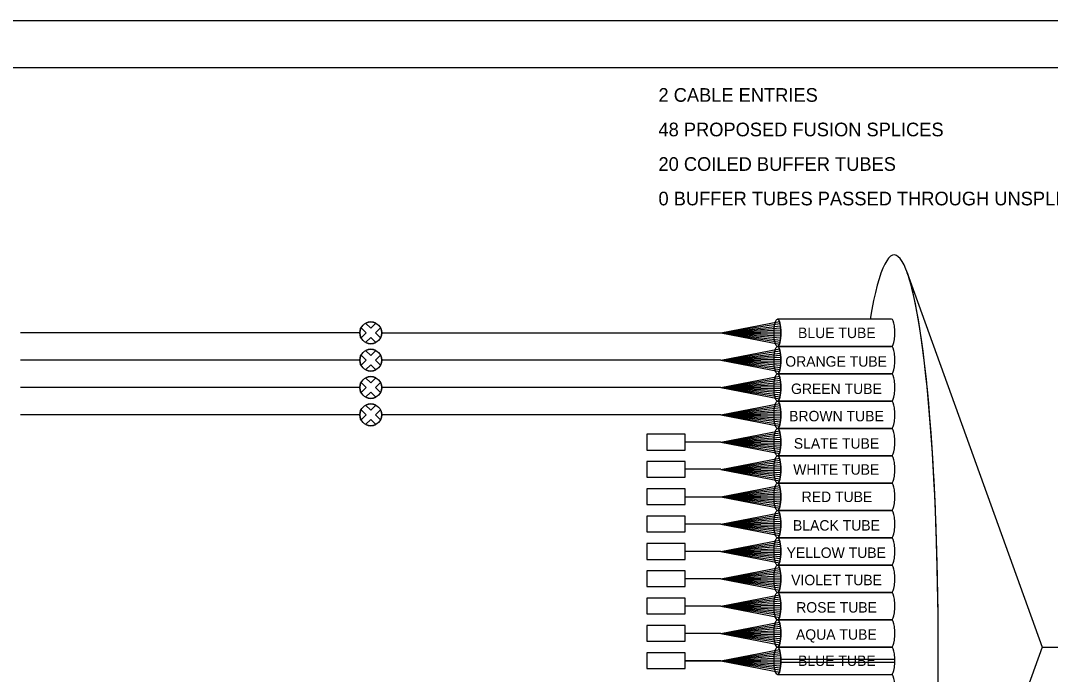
# Model space of a CAD drawing. Extents: x 1805893 to 1833564, y 708898 to 716199.
# Drawn here: x 1833208.6 to 1833434.8, y 714395 to 714538.6 of the extents above; entities that cross this region are included whole.
import ezdxf

# ---------------------------------------------------------------- set-up
doc = ezdxf.new("R2010")
doc.units = 0
doc.layers.add('BR_P_Sub_Hidden', color=7, linetype='Continuous')
doc.layers.add('SH_Data', color=7, linetype='Continuous')

msp = doc.modelspace()

# ---------------------------------------------------------------- linework, layer by layer
at = {"layer": 'BR_P_Sub_Hidden'}
for points in [[(1833067.2, 714538.6), (1833508.62, 714538.6), (1833508.62, 714273.91), (1833067.2, 714273.91)], [(1833135.95, 714528.32), (1833459.05, 714528.32), (1833459.05, 714279.3), (1833135.95, 714279.3)]]:
    msp.add_lwpolyline(points, close=True, dxfattribs=at)
at = {"layer": 'SH_Data'}
for p, q in [((1833362.41, 714470.04), (1833375.25, 714472.51)), ((1833399.88, 714473.04), (1833374.83, 714473.04)), ((1833399.88, 714473.04), (1833374.83, 714473.04)), ((1833284.46, 714470.04), (1833283.34, 714471.16)), ((1833284.46, 714470.04), (1833283.34, 714471.16)), ((1833285.48, 714471.05), (1833284.36, 714472.17)), ((1833284.36, 714472.17), (1833285.48, 714471.05)), ((1833286.6, 714472.17), (1833285.48, 714471.05)), ((1833285.48, 714471.05), (1833286.6, 714472.17)), ((1833287.61, 714471.16), (1833286.5, 714470.04)), ((1833287.61, 714471.16), (1833286.5, 714470.04)), ((1833362.41, 714470.04), (1833375.38, 714472.06)), ((1833362.41, 714470.04), (1833375.46, 714471.61)), ((1833362.41, 714470.04), (1833375.52, 714471.16)), ((1833362.41, 714470.04), (1833375.56, 714470.71)), ((1833362.41, 714470.04), (1833375.57, 714470.26)), ((1833283.07, 714470.04), (1833208.55, 714470.04)), ((1833284.46, 714470.04), (1833283.34, 714468.92)), ((1833283.34, 714468.92), (1833284.46, 714470.04)), ((1833285.48, 714469.02), (1833284.36, 714467.9)), ((1833285.48, 714469.02), (1833284.36, 714467.9)), ((1833286.6, 714467.9), (1833285.48, 714469.02)), ((1833286.6, 714467.9), (1833285.48, 714469.02)), ((1833287.61, 714468.92), (1833286.5, 714470.04)), ((1833286.5, 714470.04), (1833287.61, 714468.92)), ((1833287.89, 714470.04), (1833362.41, 714470.04)), ((1833362.41, 714470.04), (1833375.52, 714468.91)), ((1833362.41, 714470.04), (1833375.46, 714468.46)), ((1833362.41, 714470.04), (1833375.38, 714468.01)), ((1833362.41, 714470.04), (1833375.25, 714467.56)), ((1833362.41, 714470.04), (1833375.56, 714469.36)), ((1833362.41, 714470.04), (1833375.57, 714469.81)), ((1833285.48, 714465.05), (1833284.36, 714466.17)), ((1833284.36, 714466.17), (1833285.48, 714465.05)), ((1833286.6, 714466.17), (1833285.48, 714465.05)), ((1833285.48, 714465.05), (1833286.6, 714466.17)), ((1833362.41, 714464.04), (1833375.25, 714466.51)), ((1833362.41, 714464.04), (1833375.38, 714466.06)), ((1833362.41, 714464.04), (1833375.46, 714465.61)), ((1833374.83, 714467.04), (1833399.88, 714467.04)), ((1833399.88, 714467.04), (1833374.83, 714467.04)), ((1833283.07, 714464.04), (1833208.55, 714464.04)), ((1833284.46, 714464.04), (1833283.34, 714465.16)), ((1833284.46, 714464.04), (1833283.34, 714465.16)), ((1833284.46, 714464.04), (1833283.34, 714462.92)), ((1833283.34, 714462.92), (1833284.46, 714464.04)), ((1833287.61, 714465.16), (1833286.5, 714464.04)), ((1833287.61, 714465.16), (1833286.5, 714464.04)), ((1833287.61, 714462.92), (1833286.5, 714464.04)), ((1833286.5, 714464.04), (1833287.61, 714462.92)), ((1833362.41, 714464.04), (1833287.89, 714464.04)), ((1833362.41, 714464.04), (1833375.52, 714465.16)), ((1833362.41, 714464.04), (1833375.56, 714464.71)), ((1833362.41, 714464.04), (1833375.57, 714464.26)), ((1833362.41, 714464.04), (1833375.52, 714462.91)), ((1833362.41, 714464.04), (1833375.46, 714462.46)), ((1833362.41, 714464.04), (1833375.38, 714462.01)), ((1833362.41, 714464.04), (1833375.25, 714461.56)), ((1833362.41, 714464.04), (1833375.56, 714463.36)), ((1833362.41, 714464.04), (1833375.57, 714463.81)), ((1833285.48, 714463.02), (1833284.36, 714461.9)), ((1833285.48, 714463.02), (1833284.36, 714461.9)), ((1833286.6, 714461.9), (1833285.48, 714463.02)), ((1833286.6, 714461.9), (1833285.48, 714463.02)), ((1833399.88, 714461.04), (1833374.83, 714461.04)), ((1833374.83, 714461.04), (1833399.88, 714461.04)), ((1833284.46, 714458.04), (1833283.34, 714459.16)), ((1833284.46, 714458.04), (1833283.34, 714459.16)), ((1833285.48, 714459.05), (1833284.36, 714460.17)), ((1833284.36, 714460.17), (1833285.48, 714459.05)), ((1833286.6, 714460.17), (1833285.48, 714459.05)), ((1833285.48, 714459.05), (1833286.6, 714460.17)), ((1833287.61, 714459.16), (1833286.5, 714458.04)), ((1833287.61, 714459.16), (1833286.5, 714458.04)), ((1833362.41, 714458.04), (1833375.25, 714460.51)), ((1833362.41, 714458.04), (1833375.38, 714460.06)), ((1833362.41, 714458.04), (1833375.46, 714459.61)), ((1833362.41, 714458.04), (1833375.52, 714459.16)), ((1833283.07, 714458.04), (1833208.55, 714458.04)), ((1833284.46, 714458.04), (1833283.34, 714456.92)), ((1833283.34, 714456.92), (1833284.46, 714458.04)), ((1833285.48, 714457.02), (1833284.36, 714455.9)), ((1833285.48, 714457.02), (1833284.36, 714455.9)), ((1833286.6, 714455.9), (1833285.48, 714457.02)), ((1833286.6, 714455.9), (1833285.48, 714457.02)), ((1833287.61, 714456.92), (1833286.5, 714458.04)), ((1833286.5, 714458.04), (1833287.61, 714456.92)), ((1833362.41, 714458.04), (1833287.89, 714458.04)), ((1833362.41, 714458.04), (1833375.56, 714458.71)), ((1833362.41, 714458.04), (1833375.57, 714458.26)), ((1833362.41, 714458.04), (1833375.52, 714456.91)), ((1833362.41, 714458.04), (1833375.46, 714456.46)), ((1833362.41, 714458.04), (1833375.38, 714456.01)), ((1833362.41, 714458.04), (1833375.25, 714455.56)), ((1833362.41, 714458.04), (1833375.56, 714457.36)), ((1833362.41, 714458.04), (1833375.57, 714457.81)), ((1833362.41, 714452.04), (1833375.25, 714454.51)), ((1833374.83, 714455.04), (1833399.88, 714455.04)), ((1833399.88, 714455.04), (1833374.83, 714455.04)), ((1833283.07, 714452.04), (1833208.55, 714452.04)), ((1833284.46, 714452.04), (1833283.34, 714453.16)), ((1833284.46, 714452.04), (1833283.34, 714453.16)), ((1833284.46, 714452.04), (1833283.34, 714450.92)), ((1833283.34, 714450.92), (1833284.46, 714452.04)), ((1833285.48, 714453.05), (1833284.36, 714454.17)), ((1833284.36, 714454.17), (1833285.48, 714453.05)), ((1833286.6, 714454.17), (1833285.48, 714453.05)), ((1833285.48, 714453.05), (1833286.6, 714454.17)), ((1833287.61, 714453.16), (1833286.5, 714452.04)), ((1833287.61, 714453.16), (1833286.5, 714452.04)), ((1833287.61, 714450.92), (1833286.5, 714452.04)), ((1833286.5, 714452.04), (1833287.61, 714450.92)), ((1833362.41, 714452.04), (1833287.89, 714452.04)), ((1833362.41, 714452.04), (1833375.38, 714454.06)), ((1833362.41, 714452.04), (1833375.46, 714453.61)), ((1833362.41, 714452.04), (1833375.52, 714453.16)), ((1833362.41, 714452.04), (1833375.56, 714452.71)), ((1833362.41, 714452.04), (1833375.57, 714452.26)), ((1833362.41, 714452.04), (1833375.52, 714450.91)), ((1833362.41, 714452.04), (1833375.46, 714450.46)), ((1833362.41, 714452.04), (1833375.38, 714450.01)), ((1833362.41, 714452.04), (1833375.25, 714449.56)), ((1833362.41, 714452.04), (1833375.56, 714451.36)), ((1833362.41, 714452.04), (1833375.57, 714451.81)), ((1833285.48, 714451.02), (1833284.36, 714449.9)), ((1833285.48, 714451.02), (1833284.36, 714449.9)), ((1833286.6, 714449.9), (1833285.48, 714451.02)), ((1833286.6, 714449.9), (1833285.48, 714451.02)), ((1833362.41, 714446.04), (1833375.25, 714448.51)), ((1833362.41, 714446.04), (1833375.38, 714448.06)), ((1833362.41, 714446.04), (1833375.46, 714447.61)), ((1833374.83, 714449.04), (1833399.88, 714449.04)), ((1833399.88, 714449.04), (1833374.83, 714449.04)), ((1833362.41, 714446.04), (1833354.58, 714446.04)), ((1833362.41, 714446.04), (1833375.52, 714447.16)), ((1833362.41, 714446.04), (1833375.56, 714446.71)), ((1833362.41, 714446.04), (1833375.57, 714446.26)), ((1833362.41, 714446.04), (1833375.52, 714444.91)), ((1833362.41, 714446.04), (1833375.46, 714444.46)), ((1833362.41, 714446.04), (1833375.38, 714444.01)), ((1833362.41, 714446.04), (1833375.25, 714443.56)), ((1833362.41, 714446.04), (1833375.56, 714445.36)), ((1833362.41, 714446.04), (1833375.57, 714445.81)), ((1833374.83, 714443.04), (1833399.88, 714443.04)), ((1833399.88, 714443.04), (1833374.83, 714443.04)), ((1833362.41, 714440.04), (1833375.25, 714442.51)), ((1833362.41, 714440.04), (1833375.38, 714442.06)), ((1833362.41, 714440.04), (1833375.46, 714441.61)), ((1833362.41, 714440.04), (1833375.52, 714441.16)), ((1833362.41, 714440.04), (1833375.56, 714440.71)), ((1833362.41, 714440.07), (1833354.58, 714440.07)), ((1833362.41, 714440.04), (1833375.57, 714440.26)), ((1833362.41, 714440.04), (1833375.52, 714438.91)), ((1833362.41, 714440.04), (1833375.46, 714438.46)), ((1833362.41, 714440.04), (1833375.38, 714438.01)), ((1833362.41, 714440.04), (1833375.25, 714437.56)), ((1833362.41, 714440.04), (1833375.56, 714439.36)), ((1833362.41, 714440.04), (1833375.57, 714439.81)), ((1833362.41, 714434.04), (1833375.25, 714436.51)), ((1833374.83, 714437.04), (1833399.88, 714437.04)), ((1833399.88, 714437.04), (1833374.83, 714437.04)), ((1833354.58, 714434.04), (1833362.41, 714434.04)), ((1833362.41, 714434.04), (1833375.38, 714436.06)), ((1833362.41, 714434.04), (1833375.46, 714435.61)), ((1833362.41, 714434.04), (1833375.52, 714435.16)), ((1833362.41, 714434.04), (1833375.56, 714434.71)), ((1833362.41, 714434.04), (1833375.57, 714434.26)), ((1833362.41, 714434.04), (1833375.52, 714432.91)), ((1833362.41, 714434.04), (1833375.46, 714432.46)), ((1833362.41, 714434.04), (1833375.38, 714432.01)), ((1833362.41, 714434.04), (1833375.25, 714431.56)), ((1833362.41, 714434.04), (1833375.56, 714433.36)), ((1833362.41, 714434.04), (1833375.57, 714433.81)), ((1833362.41, 714428.04), (1833375.25, 714430.51)), ((1833362.41, 714428.04), (1833375.38, 714430.06)), ((1833362.41, 714428.04), (1833375.46, 714429.61)), ((1833374.83, 714431.04), (1833399.88, 714431.04)), ((1833399.88, 714431.04), (1833374.83, 714431.04)), ((1833362.41, 714428.04), (1833354.58, 714428.04)), ((1833362.41, 714428.04), (1833375.52, 714429.16)), ((1833362.41, 714428.04), (1833375.56, 714428.71)), ((1833362.41, 714428.04), (1833375.57, 714428.26)), ((1833362.41, 714428.04), (1833375.52, 714426.91)), ((1833362.41, 714428.04), (1833375.46, 714426.46)), ((1833362.41, 714428.04), (1833375.38, 714426.01)), ((1833362.41, 714428.04), (1833375.25, 714425.56)), ((1833362.41, 714428.04), (1833375.56, 714427.36)), ((1833362.41, 714428.04), (1833375.57, 714427.81)), ((1833399.88, 714425.04), (1833374.83, 714425.04)), ((1833374.83, 714425.04), (1833399.88, 714425.04)), ((1833362.41, 714422.04), (1833375.25, 714424.51)), ((1833362.41, 714422.04), (1833375.38, 714424.06)), ((1833362.41, 714422.04), (1833375.46, 714423.61)), ((1833362.41, 714422.04), (1833375.52, 714423.16)), ((1833362.41, 714422.04), (1833375.56, 714422.71)), ((1833362.41, 714422.04), (1833354.58, 714422.04)), ((1833362.41, 714422.04), (1833375.57, 714422.26)), ((1833362.41, 714422.04), (1833375.52, 714420.91)), ((1833362.41, 714422.04), (1833375.46, 714420.46)), ((1833362.41, 714422.04), (1833375.38, 714420.01)), ((1833362.41, 714422.04), (1833375.25, 714419.56)), ((1833362.41, 714422.04), (1833375.56, 714421.36)), ((1833362.41, 714422.04), (1833375.57, 714421.81)), ((1833362.41, 714416.04), (1833375.25, 714418.51)), ((1833362.41, 714416.04), (1833375.38, 714418.06)), ((1833374.83, 714419.04), (1833399.88, 714419.04)), ((1833399.88, 714419.04), (1833374.83, 714419.04)), ((1833399.88, 714419.04), (1833374.83, 714419.04)), ((1833362.41, 714416.04), (1833354.58, 714416.04)), ((1833362.41, 714416.04), (1833375.46, 714417.61)), ((1833362.41, 714416.04), (1833375.52, 714417.16)), ((1833362.41, 714416.04), (1833375.56, 714416.71)), ((1833362.41, 714416.04), (1833375.57, 714416.26)), ((1833362.41, 714416.04), (1833375.52, 714414.91)), ((1833362.41, 714416.04), (1833375.46, 714414.46)), ((1833362.41, 714416.04), (1833375.38, 714414.01)), ((1833362.41, 714416.04), (1833375.25, 714413.56)), ((1833362.41, 714416.04), (1833375.56, 714415.36)), ((1833362.41, 714416.04), (1833375.57, 714415.81)), ((1833362.41, 714410.04), (1833375.25, 714412.51)), ((1833362.41, 714410.04), (1833375.38, 714412.06)), ((1833362.41, 714410.04), (1833375.46, 714411.61)), ((1833374.83, 714413.04), (1833399.88, 714413.04)), ((1833399.88, 714413.04), (1833374.83, 714413.04)), ((1833362.41, 714410.04), (1833354.58, 714410.04)), ((1833362.41, 714410.04), (1833375.52, 714411.16)), ((1833362.41, 714410.04), (1833375.56, 714410.71)), ((1833362.41, 714410.04), (1833375.57, 714410.26)), ((1833362.41, 714410.04), (1833375.52, 714408.91)), ((1833362.41, 714410.04), (1833375.46, 714408.46)), ((1833362.41, 714410.04), (1833375.38, 714408.01)), ((1833362.41, 714410.04), (1833375.25, 714407.56)), ((1833362.41, 714410.04), (1833375.56, 714409.36)), ((1833362.41, 714410.04), (1833375.57, 714409.81)), ((1833374.83, 714407.04), (1833399.88, 714407.04)), ((1833399.88, 714407.04), (1833374.83, 714407.04)), ((1833362.41, 714404.04), (1833375.25, 714406.51)), ((1833362.41, 714404.04), (1833375.38, 714406.06)), ((1833362.41, 714404.04), (1833375.46, 714405.61)), ((1833362.41, 714404.04), (1833375.52, 714405.16)), ((1833362.41, 714404.04), (1833375.56, 714404.71)), ((1833362.41, 714404.04), (1833354.58, 714404.03)), ((1833362.41, 714404.04), (1833375.57, 714404.26)), ((1833362.41, 714404.04), (1833375.52, 714402.91)), ((1833362.41, 714404.04), (1833375.46, 714402.46)), ((1833362.41, 714404.04), (1833375.38, 714402.01)), ((1833362.41, 714404.04), (1833375.25, 714401.56)), ((1833362.41, 714404.04), (1833375.56, 714403.36)), ((1833362.41, 714404.04), (1833375.57, 714403.81)), ((1833362.41, 714398.04), (1833375.25, 714400.51)), ((1833362.41, 714398.04), (1833375.38, 714400.06)), ((1833374.83, 714401.04), (1833399.88, 714401.04)), ((1833399.88, 714401.04), (1833374.83, 714401.04)), ((1833432.95, 714401.04), (1833476.52, 714401.04)), ((1833362.41, 714398.04), (1833354.58, 714398.04)), ((1833354.58, 714398.04), (1833362.41, 714398.04)), ((1833362.41, 714398.04), (1833375.46, 714399.61)), ((1833362.41, 714398.04), (1833375.52, 714399.16)), ((1833362.41, 714398.04), (1833375.56, 714398.71)), ((1833362.41, 714398.04), (1833375.57, 714398.26)), ((1833362.41, 714398.04), (1833375.52, 714396.91)), ((1833362.41, 714398.04), (1833375.46, 714396.46)), ((1833362.41, 714398.04), (1833375.38, 714396.01)), ((1833362.41, 714398.04), (1833375.25, 714395.56)), ((1833362.41, 714398.04), (1833375.56, 714397.36)), ((1833362.41, 714398.04), (1833375.57, 714397.81)), ((1833374.83, 714395.04), (1833399.88, 714395.04))]:
    msp.add_line(p, q, dxfattribs=at)
msp.add_lwpolyline([(1833403.35, 714483.23), (1833432.95, 714401.04), (1833403.35, 714318.84)], dxfattribs=at)
msp.add_lwpolyline([(1833403.35, 714483.23), (1833432.95, 714401.04), (1833403.35, 714318.84)], dxfattribs=at)
for points in [[(1833354.58, 714444.31), (1833354.58, 714447.77), (1833346.13, 714447.77), (1833346.13, 714444.31)], [(1833354.58, 714438.31), (1833354.58, 714441.77), (1833346.13, 714441.77), (1833346.13, 714438.31)], [(1833354.58, 714432.34), (1833354.58, 714435.8), (1833346.13, 714435.8), (1833346.13, 714432.34)], [(1833354.58, 714426.35), (1833354.58, 714429.81), (1833346.13, 714429.81), (1833346.13, 714426.35)], [(1833354.58, 714420.3), (1833354.58, 714423.76), (1833346.13, 714423.76), (1833346.13, 714420.3)], [(1833354.58, 714414.31), (1833354.58, 714417.77), (1833346.13, 714417.77), (1833346.13, 714414.31)], [(1833354.58, 714408.34), (1833354.58, 714411.8), (1833346.13, 714411.8), (1833346.13, 714408.34)], [(1833354.58, 714402.34), (1833354.58, 714405.8), (1833346.13, 714405.8), (1833346.13, 714402.34)], [(1833354.58, 714396.31), (1833354.58, 714399.77), (1833346.13, 714399.77), (1833346.13, 714396.31)], [(1833400.62, 714398.34), (1833375.57, 714398.34), (1833375.57, 714397.74), (1833400.62, 714397.74)]]:
    msp.add_lwpolyline(points, close=True, dxfattribs=at)
for centre in [(1833285.48, 714470.04), (1833285.48, 714464.04), (1833285.48, 714458.04), (1833285.48, 714452.04)]:
    msp.add_circle(centre, 2.41, dxfattribs=at)
for centre, start, end in [((1833285.48, 714470.04), 62.353, 117.647), ((1833285.48, 714470.04), 152.353, 207.647), ((1833285.48, 714470.04), 332.353, 27.647), ((1833285.48, 714470.04), 242.353, 297.647), ((1833285.48, 714464.04), 62.353, 117.647), ((1833285.48, 714464.04), 152.353, 207.647), ((1833285.48, 714464.04), 332.353, 27.647), ((1833285.48, 714464.04), 242.353, 297.647), ((1833285.48, 714458.04), 152.353, 207.647), ((1833285.48, 714458.04), 62.353, 117.647), ((1833285.48, 714458.04), 332.353, 27.647), ((1833285.48, 714458.04), 242.353, 297.647), ((1833285.48, 714452.04), 62.353, 117.647), ((1833285.48, 714452.04), 152.353, 207.647), ((1833285.48, 714452.04), 332.353, 27.647), ((1833285.48, 714452.04), 242.353, 297.647)]:
    msp.add_arc(centre, 2.41, start, end, dxfattribs=at)
for centre, major_axis, ratio, start_param, end_param in [((1833400.48, 714401.04), (0, -86.09), 0.112175, 5.702888, 10.005075), ((1833400.48, 714401.04), (0, -86.09), 0.112175, 5.702888, 10.005075), ((1833400.48, 714401.04), (0, -86.09), 0.112175, 0.302036, 2.839557), ((1833374.83, 714470.04), (0, -3), 0.25, 0, 3.141593), ((1833399.88, 714470.04), (0, -3), 0.25, 0, 3.141593), ((1833399.88, 714470.04), (0, -3), 0.25, 0, 3.141593), ((1833374.83, 714464.04), (0, -3), 0.25, 0, 3.141593), ((1833399.88, 714464.04), (0, -3), 0.25, 0, 3.141593), ((1833399.88, 714464.04), (0, -3), 0.25, 0, 3.141593), ((1833374.83, 714458.04), (0, -3), 0.25, 0, 3.141593), ((1833399.88, 714458.04), (0, -3), 0.25, 0, 3.141593), ((1833399.88, 714458.04), (0, -3), 0.25, 0, 3.141593), ((1833374.83, 714452.04), (0, -3), 0.25, 0, 3.141593), ((1833399.88, 714452.04), (0, -3), 0.25, 0, 3.141593), ((1833399.88, 714452.04), (0, -3), 0.25, 0, 3.141593), ((1833374.83, 714446.04), (0, -3), 0.25, 0, 3.141593), ((1833399.88, 714446.04), (0, -3), 0.25, 0, 3.141593), ((1833399.88, 714446.04), (0, -3), 0.25, 0, 3.141593), ((1833374.83, 714440.04), (0, -3), 0.25, 0, 3.141593), ((1833399.88, 714440.04), (0, -3), 0.25, 0, 3.141593), ((1833399.88, 714440.04), (0, -3), 0.25, 0, 3.141593), ((1833374.83, 714434.04), (0, -3), 0.25, 0, 3.141593), ((1833399.88, 714434.04), (0, -3), 0.25, 0, 3.141593), ((1833399.88, 714434.04), (0, -3), 0.25, 0, 3.141593), ((1833374.83, 714428.04), (0, -3), 0.25, 0, 3.141593), ((1833399.88, 714428.04), (0, -3), 0.25, 0, 3.141593), ((1833399.88, 714428.04), (0, -3), 0.25, 0, 3.141593), ((1833374.83, 714422.04), (0, -3), 0.25, 0, 3.141593), ((1833399.88, 714422.04), (0, -3), 0.25, 0, 3.141593), ((1833399.88, 714422.04), (0, -3), 0.25, 0, 3.141593), ((1833374.83, 714416.04), (0, -3), 0.25, 0, 3.141593), ((1833399.88, 714416.04), (0, -3), 0.25, 0, 3.141593), ((1833399.88, 714416.04), (0, -3), 0.25, 0, 3.141593), ((1833374.83, 714410.04), (0, -3), 0.25, 0, 3.141593), ((1833399.88, 714410.04), (0, -3), 0.25, 0, 3.141593), ((1833399.88, 714410.04), (0, -3), 0.25, 0, 3.141593), ((1833374.83, 714404.04), (0, -3), 0.25, 0, 3.141593), ((1833399.88, 714404.04), (0, -3), 0.25, 0, 3.141593), ((1833399.88, 714404.04), (0, -3), 0.25, 0, 3.141593), ((1833374.83, 714398.04), (0, -3), 0.25, 0, 3.141593), ((1833399.88, 714398.04), (0, -3), 0.25, 0, 3.141593), ((1833399.88, 714398.04), (0, -3), 0.25, 0, 3.141593), ((1833399.88, 714392.04), (0, -3), 0.25, 0, 3.141593)]:
    msp.add_ellipse(centre, major_axis=major_axis, ratio=ratio, start_param=start_param, end_param=end_param, dxfattribs=at)
for centre in [(1833374.83, 714470.04), (1833374.83, 714464.04), (1833374.83, 714458.04), (1833374.83, 714452.04), (1833374.83, 714446.04), (1833374.83, 714440.04), (1833374.83, 714434.04), (1833374.83, 714428.04), (1833374.83, 714422.04), (1833374.83, 714416.04), (1833374.83, 714410.04), (1833374.83, 714404.04), (1833374.83, 714398.04)]:
    msp.add_ellipse(centre, major_axis=(0, -3), ratio=0.25, dxfattribs=at)

# ---------------------------------------------------------------- texts
for s, p in [('2 CABLE ENTRIES', (1833348.69, 714520.77)), ('48 PROPOSED FUSION SPLICES', (1833348.69, 714513.19)), ('20 COILED BUFFER TUBES', (1833348.69, 714505.61)), ('0 BUFFER TUBES PASSED THROUGH UNSPLICED', (1833348.69, 714498.03))]:
    msp.add_text(s, height=3, dxfattribs=at).set_placement(p)
for s, height, p in [('BLUE TUBE', 2.295, (1833379.35, 714468.89)), ('ORANGE TUBE', 2.2947, (1833376.55, 714462.61)), ('GREEN TUBE', 2.295, (1833377.81, 714456.61)), ('BROWN TUBE', 2.295, (1833377.39, 714450.61)), ('SLATE TUBE', 2.295, (1833378.42, 714444.61)), ('WHITE TUBE', 2.295, (1833378.28, 714438.89)), ('RED TUBE', 2.295, (1833380.15, 714432.89)), ('BLACK TUBE', 2.295, (1833378.24, 714426.61)), ('YELLOW TUBE', 2.2947, (1833376.83, 714420.61)), ('VIOLET TUBE', 2.2947, (1833377.84, 714414.61)), ('ROSE TUBE', 2.295, (1833378.95, 714408.61)), ('AQUA TUBE', 2.295, (1833378.9, 714402.65)), ('BLUE TUBE', 2.295, (1833379.35, 714396.89))]:
    msp.add_text(s, height=height, rotation=360, dxfattribs=at).set_placement(p)

doc.saveas('drawing.dxf')
